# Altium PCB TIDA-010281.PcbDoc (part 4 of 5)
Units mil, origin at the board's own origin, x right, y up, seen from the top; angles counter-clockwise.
Board outline 3455.86 x 1121.8 mil, 8 copper layers (Top Layer, GND1, Sig1, PWR1, PWR2, Sig2, GND2, Bottom Layer), stack 59.155 mil thick; 291 components, 180 nets, 941 pads, 539 vias.
Unrouted connection lines stored in the file: 41.
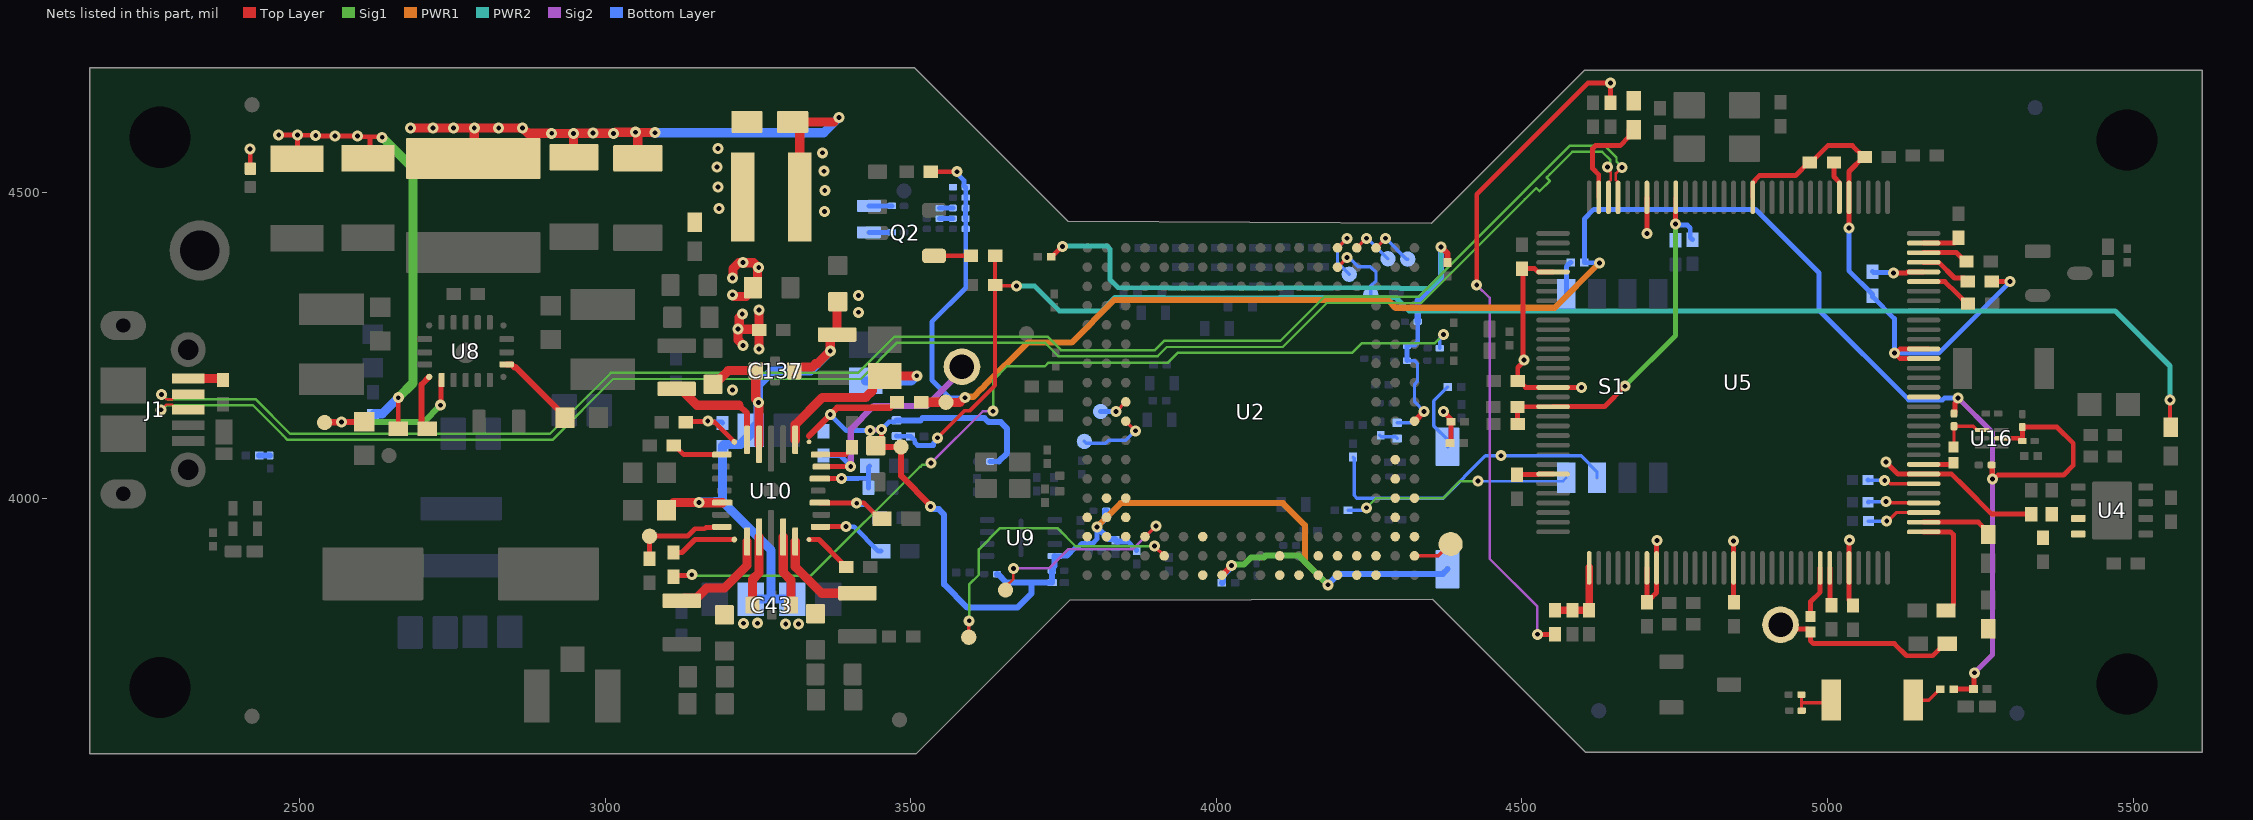
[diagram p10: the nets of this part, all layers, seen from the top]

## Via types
v1: diameter 18, hole 8, Top Layer to Bottom Layer, tented both sides, 533 vias
v2: diameter 19.68, hole 7.87, Top Layer to Bottom Layer, 5 vias
v3: diameter 17, hole 8, Top Layer to Bottom Layer, tented both sides, 1 vias

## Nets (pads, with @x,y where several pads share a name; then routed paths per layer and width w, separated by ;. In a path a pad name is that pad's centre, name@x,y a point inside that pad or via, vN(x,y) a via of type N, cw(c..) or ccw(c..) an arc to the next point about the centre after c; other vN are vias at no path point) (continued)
NetQ2_1: Q2.1 R106.2 | length 60.4
  Top Layer w8: Q2.1@3538.2,4396.29 3538.29,4396.39 3598.44,4396.39 R106.2@3598.54,4396.48
NetR2_2: R2.2 R174.1 | length 30.8
  Bottom Layer w5.5: R174.1@4267.1,4102.78 4269.74,4100.14 4293.06,4100.14 R2.2@4295.7,4097.5
NetR16_2: R16.2 S1.5 | length 55.6
  Bottom Layer w8: S1.5@4572.7,4333.33 4572.7,4378.9 4579.22,4385.42 R16.2@4580.01,4385.42
NetR51_2: R51.2 U5.33 | length 182
  Top Layer w8: U5.33@5157.18,3944.78 5201.19,3944.78 5205.88,3940.09 5205.88,3828.55 5205.59,3828.26 5205.59,3823.86 5197.78,3816.05 R51.2@5193.84,3816.05
NetR57_1: R57.1 U5.95 | length 164.5
  Top Layer w8: U5.95@4625.69,4492.02 4625.62,4492.08 4625.62,4529.3 4615.63,4539.29 4615.63,4572.01 4620.32,4576.7 4660.61,4576.7 4674.85,4590.94 4674.85,4602.5 R57.1@4676.04,4603.7
NetR63_2: R63.2 U5.34 | length 116.1
  Top Layer w8: U5.34@5157.18,3960.53 5246.65,3960.53 5262.71,3944.46 R63.2@5262.71,3940.52
NetR66_1: R66.1 U5.35 | length 96.2
  Top Layer w5.5: v1(5096.82,3962.19) 5098.35,3962.19 5112.43,3976.27 U5.35@5157.18,3976.27
  Bottom Layer w5.5: R66.1@5066.81,3962.19 v1(5096.82,3962.19)
NetR67_1: R67.1 U5.36 | length 92.2
  Top Layer w5.5: v1(5095.54,3994.44) 5097.5,3992.48 5156.73,3992.48 U5.36@5157.18,3992.02
  Bottom Layer w5.5: R67.1@5067.14,3993.8 v1@5094.9,3993.8
  Bottom Layer w8: R67.1@5066.49,3993.15 R67.1@5067.14,3993.8 ; v1@5094.9,3993.8 v1(5095.54,3994.44)
NetR69_1: R69.1 U5.38 | length 93.2
  Top Layer w5.5: v1(5093.53,4028.99) 5096.91,4028.99 5102.38,4023.52 U5.38@5157.18,4023.52
  Bottom Layer w5.5: R69.1@5066.69,4029.21 v1@5093.31,4029.21
  Bottom Layer w8: R69.1@5066.47,4029.42 R69.1@5066.69,4029.21 ; v1@5093.31,4029.21 v1(5093.53,4028.99)
NetR70_1: R70.1 U5.40 | length 50.3
  Top Layer w8: U5.40@5157.18,4055.01 5157.24,4055.08 5203.61,4055.08 R70.1@5206.3,4057.77
NetR71_2: R71.2 U5.25 | length 85.7
  Top Layer w8: R71.2@4972.14,3806.56 4972.14,3830.46 4987.89,3846.2 U5.25@4987.89,3885.72
NetR72_1: R72.1 U5.63 | length 62
  Top Layer w8: U5.63@5157.18,4417.22 5207.43,4417.22 5214.37,4424.16 R72.1@5214.37,4426.13
NetR73_1: R73.1 U5.62 | length 76.1
  Top Layer w8: U5.62@5157.18,4401.47 5210.94,4401.47 5225.37,4387.04 R73.1@5227.34,4387.04
NetR74_1: R74.1 U5.61 | length 85
  Top Layer w8: U5.61@5157.18,4385.72 U5.61@5157.18,4385.72 5182,4385.66 5207.62,4360.04 5223.3,4360.04 R74.1@5229.15,4354.19
NetR76_1: R76.1 U5.60 | length 85.3
  Top Layer w8: v1(5108.12,4368.1) 5129.12,4368.1 5130.93,4369.91 5157.12,4369.91 U5.60@5157.18,4369.97
  Bottom Layer w8: R76.1@5073.68,4370.52 5074.89,4369.31 5106.92,4369.31 v1(5108.12,4368.1)
NetR87_1: R87.1 U5.70 | length 60.9
  Top Layer w8: R87.1@5010.5,4549.28 5010.5,4525.67 5019.39,4516.78 U5.70@5019.39,4492.02
NetR90_2: R90.2 U5.59 | length 87.5
  Top Layer w8: U5.59@5157.18,4354.23 U5.59@5157.18,4354.23 5192.03,4354.16 5211.29,4334.91 5211.29,4334.84 5227.79,4318.34 R90.2@5229.76,4318.34
NetR91_2: R91.2 R141.1 U10.4 | length 160.6
  Top Layer w8: U10.4@3351.28,3992.35 3351.67,3991.96 3411.13,3991.96 v1(3411.52,3991.57) ; v1@3411.52,3992.35 3423.13,3992.35 3449.11,3966.37 R141.1@3453.05,3966.37
  Bottom Layer w8: v1(3411.52,3991.57) 3413.43,3989.66 3425.57,3989.66 3447.41,3967.81 R91.2@3449.38,3967.81
NetR92_2: R92.2 TP12.1 U10.7 | length 390.3
  Top Layer w8: U10.7@3353.74,4051.41 3354.22,4051.88 3401.38,4051.88 v1(3401.76,4051.5)
  Sig2 w10: v1(3401.76,4051.5) 3401.76,4112.92 3439.51,4150.66 3526.18,4150.66 3583.71,4208.2 TP12.1@3583.71,4214.86
  Bottom Layer w8: R92.2@3357.44,4069.66 3384.6,4069.66 3401.76,4052.51 v1(3401.76,4051.5)
NetR94_2: R94.2 U10.16 | length 84.9
  Top Layer w8: R94.2@3112.06,4085.88 3114.03,4085.88 3128.82,4071.09 U10.16@3190.85,4071.09
NetR110_1: R110.1 U8.1 | length 95.5
  Top Layer w10: R110.1@2708.74,4113.26 2706.28,4113.26 2699.47,4120.07 2699.47,4185.71 U8.1@2712.02,4198.31 U8.1@2712.02,4198.31
NetR111_1: R111.1 SW3.2 | length 51.6
  Top Layer w5.5: SW3.2@5140.04,3669.47 5165.61,3669.47 5183.47,3687.32 R111.1@5184.25,3687.32
NetR113_2: R113.2 TP1.1 U8.2 | length 280.7
  Top Layer w8: v1(2730.48,4151.88) 2731.52,4152.93 2731.52,4192.22 U8.2@2732.45,4193.15
  Top Layer w10: TP1.1@2540.97,4123.57 2541.39,4123.99 2568.46,4123.99 v1(2568.88,4124.41) 2605.37,4124.41 R113.2@2605.99,4125.03
  Sig1 w10: v1(2568.88,4124.41) 2703,4124.41 v1(2730.48,4151.88)
NetR125_2: R125.2 R129.1 SW3.1 | length 77
  Top Layer w5.5: R125.2@4957.26,3678.43 4957.37,3678.32 4957.37,3665.25 ; R129.1@4957.48,3652.08 4957.37,3652.18 4957.37,3665.25 ; SW3.1@5006.18,3669.47 5001.97,3665.25 4957.37,3665.25
NetR127_2: R127.2 U10.23 | length 108.1
  Top Layer w8: R127.2@3112.06,3910.9 3125.64,3910.9 3146.87,3932.13 U10.23@3211.33,3932.13
NetR131_2: R131.2 TP10.1 U10.22 | length 161.3
  Top Layer w8: R131.2@3072.69,3900.86 TP10.1@3072.69,3937.64 3134.7,3937.64 3146.89,3949.83 3162.88,3949.83 3165.12,3952.06 3189.93,3952.06 U10.22@3190.85,3952.98
NetR134_1: R134.1 U10.1 | length 80.7
  Top Layer w8: U10.1@3333.5,3932.13 3349.87,3932.13 3386.71,3895.29 3386.71,3893.32 3392.55,3887.48 R134.1@3394.52,3887.48
NetR136_1: R136.1 U10.8 | length 57.9
  Top Layer w8: U10.8@3352.27,4071.09 3393.71,4071.09 3403.94,4081.33 R136.1@3403.94,4083.29
NetR139_2: R139.2 U10.2 | length 115.5
  Top Layer w8: U10.2@3352.27,3952.98 3352.46,3953.18 3393.84,3953.18 v1(3394.04,3953.38)
  Bottom Layer w8: v1(3394.04,3953.38) 3394.43,3952.99 3407.35,3952.99 3447.06,3913.28 R139.2@3451,3913.28
NetR176_1: R176.1 S3.1 | length 117
  Bottom Layer w5.5: S3.1@4378.33,4083.66 4378.33,4095.26 4355.69,4117.91 4355.69,4158.92 R176.1@4378.58,4181.8
NetTP2_1: TP2.1 U2.C10 | length 47.8
  Top Layer w5.5: v1(3836.01,4141.61) U2.C10@3851.76,4157.36
  Bottom Layer w8: TP2.1@3810.59,4141.77 3835.85,4141.77 v1(3836.01,4141.61)
NetTP3_1: TP3.1 U2.C9 | length 115.7
  Top Layer w5.5: U2.C9@3851.76,4125.86 v1(3867.5,4110.11)
  Bottom Layer w5.5: TP3.1@3784,4092.76 3787.31,4089.45 3818.58,4089.45 3823.59,4094.46 3851.85,4094.46 v1(3867.5,4110.11)
NetTP6_1: TP6.1 U2.T18 | length 72.5
  Top Layer w5.5: U2.T18@4261.2,4409.33 v1(4276.95,4425.07)
  Bottom Layer w5.5: v1(4276.95,4425.07) 4311.08,4390.94 TP6.1@4313,4390.94
NetTP7_1: TP7.1 U2.R18 | length 71.4
  Top Layer w5.5: U2.R18@4229.71,4409.33 v1(4245.46,4425.07)
  Bottom Layer w5.5: v1(4245.46,4425.07) 4247.21,4425.07 TP7.1@4280.69,4391.59
NetTP8_1: TP8.1 U2.P17 | length 119.9
  Top Layer w5.5: U2.P17@4198.21,4377.83 v1(4213.96,4393.58)
  Bottom Layer w5.5: v1(4213.96,4393.58) 4217.13,4393.58 4231.98,4378.73 4251.94,4378.73 4261.2,4369.47 4261.2,4355.69 4252.7,4347.19 TP8.1@4252.7,4332.6
NetTP9_1: TP9.1 U2.P18 | length 95.6
  Top Layer w5.5: U2.P18@4198.21,4409.33 v1(4213.96,4425.07)
  Bottom Layer w5.5: v1(4213.96,4425.07) 4198.22,4409.33 4198.22,4385.27 TP9.1@4217.3,4366.19
NetTP11_1: TP11.1 U2.V2 | length 67.1
  Top Layer w5.5: U2.V2@4324.2,3905.39 4363.06,3905.39 4382.34,3924.67 TP11.1@4383.28,3924.67
NetTP23_1: TP23.1 U2.E2 | length 487.3
  Top Layer w5.5: TP23.1@3594.89,3772.36 3594.89,3798.48 v1(3595.64,3799.22) ; v1(3898.66,3921.37) v1(3898.66,3921.37) U2.E2@3914.75,3905.39 U2.E2@3914.75,3905.39
  Sig1 w4.2: v1@3595.41,3799.22 3595.41,3858.46 3611.5,3874.56 3611.5,3915.97 3646.32,3950.8 3740,3950.8 3769.66,3921.14 3898.43,3921.14 v1(3898.66,3921.37)
NetTP24_1: TP24.1 U2.D3 | length 327.5
  Top Layer w4.2: TP24.1@3655,3849.49 3655,3855.11 3667.82,3867.93 v1(3667.82,3885.04)
  Top Layer w5.5: U2.D3@3883.25,3936.89 3883.51,3936.89 3900.74,3954.12 v1(3901,3954.12)
  Sig2 w4.2: v1(3667.82,3885.04) 3726.36,3885.04 3757.68,3916.36 3863.24,3916.36 v1(3901,3954.12)
NetU2_A3: U2.A3
NetU2_A4: U2.A4
NetU2_B3: U2.B3
NetU2_B4: U2.B4
NetU2_B5: U2.B5
NetU2_C3: U2.C3
NetU2_C4: U2.C4
NetU2_C5: U2.C5
NetU2_G1: U2.G1
NetU2_G3: U2.G3
NetU2_L1: U2.L1
NetU2_L2: U2.L2
NetU2_M1: U2.M1
NetU2_N1: U2.N1
NetU2_N2: U2.N2
NetU2_P1: U2.P1
NetU2_P2: U2.P2
NetU2_R1: U2.R1
NetU2_R2: U2.R2
NetU2_T1: U2.T1
NetU2_T2: U2.T2
NetU2_U3: U2.U3
NetU2_U4: U2.U4
NetU2_U5: U2.U5
NetU2_U6: U2.U6
NetU2_U7: U2.U7
NetU2_V3: U2.V3
NetU2_V5: U2.V5
nFAULT: R114.2 U8.8 | length 132.9
  Top Layer w10: U8.8@2838.75,4218.74 2846.73,4218.74 2851.49,4213.97 2853.54,4213.97 2923.35,4144.17 2923.35,4141.91 R114.2@2934.1,4131.16
NRSTOUT: R95.2 R97.2 U10.6 | length 116.5
  Top Layer w8: U10.6@3351.28,4031.72 3351.59,4032.03 3386.41,4032.03 v1(3386.72,4032.33)
  Bottom Layer w8: v1@3387.01,4032.04 3414,4032.04 3414.45,4032.5 3430.69,4032.5 ; R97.2@3430.69,4016.69 3430.69,4032.11 3430.69,4050.47 R95.2@3432.95,4052.72
PGOOD: R18.1 R106.1 R112.2 R118.1 R119.2 | length 2522.3
  Top Layer w6: v1(3543.56,4098.62) 3587.56,4142.62 3596.2,4142.62 3637.91,4184.32 R112.2@3637.91,4348.49 ; R106.1@3637.91,4396.48 R112.2@3637.91,4348.49 ; v1(3672.85,4347.25) 3639.14,4347.25 R112.2@3637.91,4348.49 ; v1(5560.35,4160.61) 5560.35,4116.94 R18.1@5561.26,4116.03
  PWR2 w8: v1(3672.85,4347.25) 3702.15,4347.25 3743.21,4306.19 3812.27,4306.19 3834.16,4328.08 3915.53,4328.08 3916.17,4327.45 4102.47,4327.45 4103.11,4328.08 4136.33,4328.08 4136.47,4327.94 4196.96,4327.94 4197.1,4328.08 4293.3,4328.08 4315.19,4306.19 5470.25,4306.19 5560.35,4216.09 v1(5560.35,4160.61)
  Bottom Layer w8: R118.1@3476.67,4101.6 3477.18,4101.09 3499.01,4101.09 R119.2@3499.52,4100.58 3500.31,4100.58 3506.48,4094.41 3506.48,4090.97 3511.17,4086.29 3537.17,4086.29 3537.17,4089.52 3543.56,4095.91 v1(3543.56,4098.62)
PMIC_3V3: C87.1 C88.1 C100.1 C101.1 C102.1 C108.2 L12.1 R2.1 R4.1 R5.1 R9.1 R21.2 R22.2 R23.2 R43.2 R44.2 R45.2 R59.2 R75.1 R118.2 S3.2 TP22.1 U2.H1 U2.V9 U9.8 U10.9 | length 3607.2
  Top Layer w8: C108.2@3442.7,4085.55 3452.05,4094.9 v1(3452.05,4112.26) ; R4.1@3729.77,4394.61 3730.56,4394.61 3747.84,4411.89 v1(3748.45,4411.89) ; v1(4371.44,4141.61) 4383.88,4129.17 C88.1@4383.88,4124.76 4383.88,4094.76 C102.1@4379.37,4090.24
  Top Layer w10: 3333.5,4101.76 3379.44,4147.7 3466.41,4147.7 3475.47,4156.76 L12.1@3477.44,4156.76 ; C108.2@3444.51,4083.73 TP22.1@3484.04,4083.73 3484.04,4036.21 3532.57,3987.67 v1(3532.57,3985.89) ; U2.H1@4009.24,3873.89 v1(4024.98,3889.64) ; U2.V9@4324.2,4125.86 v1(4339.94,4141.61) ; v1(4367.63,4410.91) 4378.13,4400.41 R5.1@4378.13,4385.29
  Sig1 w10: v1(4024.98,3889.64) 4026.51,3891.17 4045.15,3891.17 4056.59,3902.61 4077.62,3902.61 4080.73,3905.71 4134.9,3905.71 v1(4182.46,3858.15)
  PWR1 w10: v1(3804.51,3952.63) 3843.5,3991.63 4108.76,3991.63 4144.85,3955.54 4144.85,3895.76 v1(4182.46,3858.15)
  PWR2 w8: v1(3748.45,4411.89) 3749.13,4412.58 3821,4412.58 3825.69,4407.89 3825.69,4357.6 3839.21,4344.08 3922.16,4344.08 3922.79,4343.45 4095.85,4343.45 4096.48,4344.08 4142.96,4344.08 4143.1,4343.94 4190.33,4343.94 4190.47,4344.08 4299.92,4344.08 4300.92,4343.08 4347.81,4343.08 4367.63,4362.9 v1(4367.63,4410.91)
  Sig2 w8: v1(3433.61,4110.29) 3434.6,4111.28 3451.07,4111.28 v1(3452.05,4112.26)
  Bottom Layer w5.5: R2.1@4295.7,4123.1 4321.43,4123.1 v1(4339.94,4141.61) 4324.2,4157.36 4324.2,4186.5 4329,4191.3 4329,4220.2 4324.44,4224.76 R59.2@4311.76,4224.76
  Bottom Layer w8: v1(3368.32,4136.58) 3394.6,4110.29 v1(3433.61,4110.29) ; v1(3452.05,4112.26) 3452.05,4112.45 3464.46,4124.85 3474.33,4124.85 R118.2@3476.67,4127.2 ; R44.2@3629.89,4059.85 3643.99,4059.85 ; U9.8@3735.4,3905.15 3755.66,3905.15 3769.33,3918.82 3772.88,3918.82 3779.79,3925.72 3797.44,3925.72 3804.51,3932.79 v1(3804.51,3952.63) ; 3854.71,3929.13 3866.52,3917.33 3867.3,3917.33 3869.6,3915.03 R75.1@3869.6,3914.24 ; R59.2@4311.76,4224.76 R23.2@4311.76,4249.29 4313.12,4250.65 4324.8,4250.65 4329.48,4255.34 R22.2@4329.48,4288.76
  Bottom Layer w10: R118.2@3476.67,4127.2 3515.41,4127.2 3519.23,4131.02 3620.43,4131.02 3627.23,4124.22 3647.19,4124.22 3657.68,4113.73 3657.68,4073.54 3643.99,4059.85 ; v1(3532.57,3985.89) 3533.39,3985.89 3537.46,3981.82 3545.88,3981.82 3554.66,3973.03 3554.66,3858.85 3592.64,3820.87 3674.32,3820.87 3697.56,3844.12 3697.56,3861.85 ; R43.2@3641.22,3875.43 3641.58,3875.06 3642.87,3875.06 3656.09,3861.85 3697.56,3861.85 ; C101.1@3730.99,3881.17 C101.1@3731.2,3881.17 ; U9.8@3735.4,3905.15 3735.4,3889.28 3732.96,3886.83 3732.96,3881.34 3732.79,3881.17 C101.1@3731.2,3881.17 ; R45.2@3819.73,3978.91 3818.44,3978.91 3818.08,3978.55 3818.08,3966.2 v1(3804.51,3952.63) 3823.84,3933.31 3833.7,3933.31 3835,3932.01 R9.1@3835,3931.22 ; R9.1@3835,3930.43 3836.3,3929.13 3854.71,3929.13 ; C87.1@4008.95,3861.38 4009.74,3861.38 4011.04,3862.68 4011.04,3873.53 4024.98,3887.48 v1(4024.98,3889.64) ; v1(4182.46,3858.15) 4200.36,3876.05 4370.48,3876.05 S3.2@4378.13,3883.7 ; R22.2@4329.48,4288.76 R21.2@4329.48,4310.76 4329.48,4322.94 4367.63,4361.09 v1(4367.63,4410.91) ; 3697.56,3861.85 3697.64,3861.77 3731.29,3861.77 C100.1@3731.37,3861.69 3731.37,3880.99 C101.1@3731.2,3881.17
PMIC_5V0: C106.1 C107.1 U10.10 | length 347.6
  Top Layer w15: U10.10@3310.93,4095.21 3310.93,4120.1 3355.53,4164.7 3426.34,4164.7 3437.56,4175.92 3437.56,4185.56 C106.1@3454.51,4202.5 ; C106.1@3457.62,4199.71 3457.82,4199.9 3509.61,4199.9 v1(3509.81,4200.09)
  Bottom Layer w15: C107.1@3426.34,4191.6 3500.5,4191.6 3508.99,4200.09 v1(3509.81,4200.09)
PMIC_CLK: R103.2 R127.1 | length 1479.1
  Top Layer w8: R127.1@3112.06,3871.53 3113.59,3873.07 3140.16,3873.07 v1(3141.7,3874.61)
  Sig1 w4.2: v1(3141.7,3874.61) 3143.34,3872.97 3336.66,3872.97 3514.92,4051.23 3515.96,4051.23 3519.3,4054.56 3530.72,4054.56 v1(3533.36,4057.2) ; v1(3634.65,4142.12) 3634.65,4192.45 3657.87,4215.67 3719.34,4215.67 3725.17,4221.5 3920.94,4221.5 3937.37,4237.93 4222.5,4237.93 4237.56,4252.99 4356.92,4252.99 v1(4371.44,4267.52)
  Sig2 w4.2: v1(3533.36,4057.2) 3618.21,4142.05 v1(3634.65,4142.12) v1(3634.65,4142.12)
  Bottom Layer w5.5: R103.2@4365.65,4245.1 4365.65,4261.72 v1(4371.44,4267.52)
PMIC_EN: R122.1 R123.1 U10.15 | length 120.5
  Top Layer w8: R122.1@3131.74,4124.03 3132.86,4125.14 3166.7,4125.14 v1(3167.82,4126.26) 3169.73,4124.34 3178.94,4124.34 U10.15@3211.33,4091.95
  Bottom Layer w8: v1(3167.82,4126.26) 3169.53,4124.54 3190.49,4124.54 R123.1@3192.2,4122.83
PMIC_INPUT3V3: C131.1 C132.2 C133.2 C134.2 C135.1 L6.2 L8.1 R110.2 R115.2 R120.1 | length 1886.9
  Top Layer w8: v1(2419.11,4570.98) 2419.22,4570.87 2419.22,4538.94 C132.2@2419.33,4538.83 ; v1(2465.87,4593.78) 2466,4593.92 2496.7,4593.92 v1(2496.84,4594.05) ; C135.1@2495.65,4555.28 2496.84,4556.47 v1(2496.84,4594.05) ; C131.1@2611.98,4555.81 2615.09,4558.92 2615.09,4591.18 ; v1(2635.18,4590.27) 2634.27,4591.18 2615.09,4591.18 ; R110.2@2661.5,4113.26 v1(2661.5,4164.2) ; v1(2496.84,4594.05) 2497.25,4593.64 2526,4593.64 v1(2526.41,4593.22) 2526.97,4592.66 2557.67,4592.66 v1(2558.23,4592.1) v1(2595,4592.1) 2595.92,4591.18 2615.09,4591.18
  Top Layer w15: v1(2681.59,4605.33) v1(2718.37,4605.33) v1(2751.54,4605.33) v1(2785.84,4605.33) ; L6.2@2784.02,4555.53 2785.84,4557.35 v1(2785.84,4605.33) ; C133.2@2948.98,4557.72 2948.28,4558.42 v1(2948.28,4596.6) ; v1@3050.07,4598.14 3081.05,4598.14 v1(3081.47,4597.71) ; C134.2@3053.4,4555.84 3053.4,4593.99 3049.65,4597.75 v1(3049.65,4598.56) 3016.67,4598.56 3014.7,4596.59 v1(3013.89,4596.59) 3013.61,4596.87 2980.09,4596.87 v1(2979.81,4597.15) 2979.53,4596.87 2948.56,4596.87 v1(2948.28,4596.6) ; R120.1@3306.67,4615.45 R120.1@3307.6,4615.45 ; L8.1@3318.21,4492.76 3318.21,4604.84 R120.1@3307.6,4615.45 ; 3374.45,4615.45 R120.1@3307.6,4615.45 ; v1(2785.84,4605.33) v1(2825.8,4605.33) v1(2864.39,4605.33) 2865.21,4605.33 2873.66,4596.88 v1(2912.51,4596.88) 2912.65,4596.74 2948.14,4596.74 v1(2948.28,4596.6)
  Sig1 w15: v1(2635.18,4590.27) 2685.56,4539.9 2685.56,4188.25 v1(2661.5,4164.2)
  Bottom Layer w15: R115.2@2620.02,4133.57 2622.36,4135.91 2622.36,4137.88 2635.18,4137.88 v1(2661.5,4164.2) ; v1(3081.47,4597.71) 3357.53,4597.71 v1(3382.35,4622.54)
  other v1: 3358.95,4468.57 3359.32,4503.46 3358.04,4534.73 3355.86,4564.9
PMIC_NINT: R92.1
PS0: R77.2 R93.1 | length 21.6
  Bottom Layer w8: R93.1@3547.14,4457.3 R77.2@3568.78,4457.3
PS1: R78.2 R98.1 | length 21.7
  Bottom Layer w8: R98.1@3547.14,4474.39 3547.22,4474.47 3568.69,4474.47 R78.2@3568.77,4474.55
PVIN3V3: C27.2 C28.2 C29.2 C35.2 C36.1 C37.1 C40.1 C41.1 C42.1 C43.1 C43.3 C48.2 C105.2 C137.1 C137.3 L8.2 L11.2 R120.2 R123.2 U10.13 U10.20 U10.25 U10.27 | length 1660.7
  Top Layer w15: C48.2@3100.25,3980.41 3100.25,3981.39 3108.49,3989.64 3109.28,3989.64 3112.21,3992.57 v1(3153.42,3992.57) 3153.53,3992.46 3191.72,3992.46 U10.20@3191.83,3992.35 ; C28.2@3176.45,4186.04 3184.7,4194.29 3187.1,4194.29 3201.29,4208.47 C137.3@3246.07,4208.47 ; v1(3208.36,4332.59) 3209.17,4332.59 3212.07,4329.69 3230.18,4329.69 3241.85,4341.37 C27.2@3241.85,4344.32 3249.12,4351.58 3249.12,4374.32 3251.22,4376.43 v1(3251.22,4377.24) 3250.41,4377.24 3242.71,4384.94 3226.72,4384.94 v1@3225.93,4385.72 ; v1(3208.44,4360.07) 3209.01,4360.64 3209.01,4375.23 3218.72,4384.94 3224.76,4384.94 v1(3225.33,4385.51) ; v1@3218,4276.15 C37.1@3250.87,4276.15 ; v1(3224.33,4301.35) 3224.33,4300.54 3219.39,4295.6 3219.39,4279.5 3217.42,4277.53 v1(3217.42,4276.72) 3217.42,4258.55 3225.33,4250.64 v1(3225.33,4249.83) ; C43.3@3241.07,3824.82 3241.07,3866.77 3251.87,3877.57 U10.25@3251.87,3936.25 ; C137.3@3246.39,4208.15 3246.39,4161.84 v1@3250.95,4157.27 ; U10.13@3251.87,4087.83 3251.87,4154.73 3251.53,4155.07 3251.53,4155.19 v1@3251.87,4155.54 ; v1(3251.87,4244.1) C37.1@3251.87,4274.8 3251.87,4275.14 C37.1@3250.87,4276.15 ; v1(3251.87,4307.72) 3251.87,4277.15 C37.1@3250.87,4276.15 ; U10.27@3291.24,3936.25 3291.24,3878.58 3304.06,3865.76 C43.1@3304.06,3824.82 ; C137.1@3309.38,4210.12 3313.69,4214.43 3338.92,4214.43 3344.36,4219.87 3347.06,4219.87 3367.51,4240.31 v1(3368.32,4240.31) 3368.32,4263.11 3372.63,4267.43 L11.2@3379.44,4267.43 C105.2@3379.44,4321.35
  Bottom Layer w15: v1(3153.42,3992.57) 3153.99,3993.15 3178.97,3993.15 3179.78,3993.95 3192.2,3993.95 ; C42.1@3238.37,3834.64 3271.56,3834.64 ; C41.1@3306.01,3834.64 3271.56,3834.64 ; v1(3368.32,4240.31) 3335.8,4207.8 3272.92,4207.8 3250.95,4185.83 v1(3250.95,4156.46) 3250.38,4155.89 3250.38,4122.8 C40.1@3238.3,4110.72 3238.3,4104.82 3221.25,4087.77 3194.54,4087.77 3192.2,4085.43 R123.2@3192.2,4083.46 3192.2,3993.95 ; 3192.2,3993.95 3271.56,3914.6 3271.56,3834.64
  other v1: 3295.34,3794.26 3316.2,3794.2 3226.17,3795.1 3249.06,3795.22 3208.44,4176.61 3414.61,4303.98 3414.42,4331.13 3186.1,4473.47 3184.83,4508.74 3183.01,4541.45 3184.83,4572.17
SENS_NRST: R81.2
SOP0: R159.2 S1.3 | length 512.2
  Bottom Layer w5.5: R159.2@4223.5,4067.08 4225.4,4065.18 4225.4,4004.31 4229.83,3999.88 4351.98,3999.88 ; 4351.98,3999.98 4370.9,3999.98 4440.23,4069.31 v1(4465.99,4069.31) 4596.72,4069.31 4622.7,4043.33 S1.3@4622.7,4033.33
SOP1: R171.2 S1.4 | length 379.3
  Sig1 w4.2: v1(4245.46,3984.13) 4260.76,3999.43 4370.7,3999.43 4398.98,4027.72 v1(4428.21,4027.72)
  Bottom Layer w4.2: v1(4428.21,4027.72) 4567.09,4027.72 S1.4@4572.7,4033.33
  Bottom Layer w5.5: R171.2@4215.47,3980.18 4241.5,3980.18 v1(4245.46,3984.13)
SW_B1: L7.1 U10.28 | length 160.9
  Top Layer w15: U10.28@3310.93,3928.87 3310.93,3887.64 3354.26,3844.3 L7.1@3412.67,3844.3
SW_B2: L9.1 U10.24 | length 169.9
  Top Layer w15: L9.1@3125.31,3832.01 3129.63,3836.32 3149.31,3836.32 3165.73,3852.74 3195.09,3852.74 3232.19,3889.84 U10.24@3232.19,3928.87
SW_B3: L10.1 U10.14 | length 185.7
  Top Layer w10: 3218.72,4151.88 3232.19,4138.42 U10.14@3232.19,4095.21
  Top Layer w15: L10.1@3106.76,4179.55 3122.48,4179.55 3150.15,4151.88 3218.72,4151.88
USB_5V: FL2.1 J1.1 | length 58.3
  Top Layer w15: J1.1@2317.73,4195.71 2372.54,4195.71 2374.88,4193.37 FL2.1@2374.88,4193.19
USB_DM: J1.2 U5.93 | length 2754.5
  Top Layer w4: v1(2273.98,4169.36) 2281.76,4161.58 2291.46,4161.58 2300.01,4170.12 J1.2@2317.73,4170.12 ; U5.93@4657.18,4492.02 4657.18,4516.3 4653.56,4519.92 4653.56,4531.32 4663.16,4540.92 v1(4663.71,4540.92)
  Sig1 w4: v1(2273.98,4169.36) 2275.85,4169.36 2283.32,4161.88 2427.86,4161.88 2484.49,4105.26 2909.51,4105.26 3009.08,4204.84 3413.93,4204.84 3473.46,4264.38 3473.56,4264.28 3723.4,4264.28 3745.55,4242.13 3899.6,4242.13 3914.6,4257.13 4104.44,4257.13 4176.5,4329.19 4330.97,4329.19 4578.48,4576.7 4635.24,4576.7 4654.66,4557.27 4654.66,4550.36 4663.71,4541.32 v1(4663.71,4540.92)
USB_DP: J1.3 U5.94 | length 2750.7
  Top Layer w4: v1(2273.44,4144.41) 2273.44,4144.76 2281.76,4153.08 2291.75,4153.08 2300.3,4144.53 J1.3@2317.73,4144.53 ; v1(4639.83,4541.77) 4639.83,4537.98 4645.06,4532.75 4645.06,4519.92 4641.43,4516.3 U5.94@4641.43,4492.02
  Sig1 w4: v1(2273.44,4144.41) 2275.31,4144.41 2282.78,4151.88 2423.72,4151.88 2472.77,4102.83 2480.34,4095.26 2913.65,4095.26 3013.23,4194.84 3418.07,4194.84 3477.51,4254.28 3719.25,4254.28 3741.41,4232.13 3903.75,4232.13 3918.75,4247.13 4108.58,4247.13 4180.64,4319.19 4335.11,4319.19 4504.89,4488.96 4523.27,4507.35 4528.67,4501.95 4545.64,4518.92 4540.24,4524.32 4545.68,4529.75 4582.63,4566.7 4631.1,4566.7 4644.66,4553.13 4644.66,4549.82 4639.83,4544.98 v1(4639.83,4541.77)
VBUS: R64.2 R65.2 | length 17.9
  Bottom Layer w10: R64.2@2433.88,4069.66 2433.95,4069.59 2451.64,4069.59 R65.2@2451.72,4069.52
VBUS_1_DETECT: C16.2 R17.1 R29.2 U5.1 | length 126.8
  Top Layer w12: R17.1@4554.01,3816.35 C16.2@4582.9,3816.35 R29.2@4609.94,3816.35 U5.1@4609.94,3885.72 U5.1@4609.94,3887.25
VCC_BA_3V3: C72.2 L12.2 R13.1 R16.1 R77.1 R78.1 R80.1 R81.1 R82.1 R104.2 R111.2 R124.2 R177.1 R178.1 TP16.1 U16.5 | length 3501.1
  Top Layer w8: R104.2@3533,4533.92 v1(3575.52,4533.92) ; R111.2@5206.3,3687.32 5206.47,3687.49 5238.53,3687.49 R13.1@5238.69,3687.65 5239.54,3688.51 5239.54,3713.26 v1(5240.39,3714.11) ; R177.1@5206.87,4138.44 5208.24,4139.8 5208.24,4155.59 5213.53,4160.88 v1(5213.53,4163.59) ; R178.1@5268.42,4054.09 5269.14,4053.37 5269.14,4032.1 v1(5269.86,4031.37) 5272.57,4031.37 5278.75,4037.55 5386.08,4037.55 5401.95,4053.42 5401.95,4089.6 5375.42,4116.14 R124.2@5318.65,4116.14 C72.2@5318.65,4093.48 5317.48,4094.65 5315.68,4094.65 5312.46,4097.87 U16.5@5284.42,4097.87
  Top Layer w15: L12.2@3516.89,4156.69 TP16.1@3557.44,4156.69 ; TP16.1@3557.51,4156.59 3580.18,4156.59 3587.79,4164.2 v1(3588.6,4164.2)
  PWR1 w10: v1(3588.6,4164.2) 3590.13,4165.73 3602.8,4165.73 3615.55,4178.49 ccw(c3587.75,4211.29) 3620.55,4183.49 3691.44,4254.38 3763.01,4254.38 3832.9,4324.27 4280.06,4324.27 4292.99,4311.34 4553.57,4311.34 v1(4626.81,4384.58)
  Sig2 w8: v1(5213.53,4163.59) 5269.86,4107.25 v1(5269.86,4031.37) 5269.86,3743.58 v1(5240.39,3714.11)
  Bottom Layer w8: v1(3575.52,4533.92) 3575.52,4531.21 3587.32,4519.41 3587.32,4510.18 3588.68,4508.82 R81.1@3589.97,4508.82 R82.1@3589.97,4491.64 3589.89,4491.56 3589.89,4474.63 R78.1@3589.81,4474.55 R77.1@3589.82,4457.3 ; v1(3588.6,4164.2) 3588.46,4164.05 3563.6,4164.05 3534.52,4193.14 3534.52,4288.35 3589.88,4343.72 R80.1@3589.88,4440.29 ; R80.1@3589.88,4440.29 R77.1@3589.85,4457.27 ; v1(4626.81,4384.58) 4626.39,4385 4602.48,4385 R16.1@4602.06,4385.42 4602.06,4456.66 4617.75,4472.36 4882.06,4472.36 4986.02,4368.4 4986.02,4307.3 5132.71,4160.61 5188.53,4160.61 5191.5,4163.59 v1(5213.53,4163.59)
VCC_XDS_3V3: C7.2 C8.2 C9.1 C10.2 C11.1 C12.1 C13.2 C15.2 R20.2 R68.1 R74.2 R76.2 R87.2 R89.2 U4.3 U4.4 U5.7 U5.8 U5.16 U5.26 U5.28 U5.39 U5.47 U5.51 U5.52 U5.69 U5.79 U5.90 U5.101 U5.113 U5.122 | length 2159.6
  Top Layer w8: C10.2@4491.53,4038.27 4526.39,4038.27 4527.39,4039.27 U5.122@4550.88,4039.27 ; U5.101@4550.88,4369.97 4550.82,4370.04 4526.06,4370.04 4520.69,4375.41 C9.1@4499.97,4375.41 4501.71,4373.68 4501.71,4227.68 v1(4503.44,4225.94) 4503.44,4224 4493.09,4213.65 C12.1@4493.09,4191.81 4495.06,4191.81 4505.86,4181 U5.113@4550.88,4181 v1(4597.22,4181) ; U5.7@4704.43,3885.72 4704.49,3885.66 4704.49,3830.12 R89.2@4704.82,3829.79 4704.82,3831.76 4710.66,3837.6 4712.63,3837.6 4720.17,3845.14 U5.8@4720.17,3885.72 4720.24,3885.79 4720.24,3929.97 v1(4720.7,3930.44) ; U5.90@4704.43,4492.02 4704.49,4491.96 4704.49,4433.3 v1(4704.82,4432.97) ; U5.16@4846.16,3885.72 U5.16@4846.16,3885.72 4846.22,3829.71 C8.2@4846.59,3829.34 ; U5.16@4846.14,3885.74 v1(4846.12,3929.8) ; U5.79@4877.65,4492.02 4877.65,4515.52 4881.47,4519.33 4881.47,4520.59 4888.46,4527.58 4947.46,4527.58 4969.16,4549.28 R87.2@4971.13,4549.28 4973.1,4549.28 5000.52,4576.7 5040.61,4576.7 5059.04,4558.28 5035.13,4534.37 U5.69@5035.13,4492.02 U5.69@5035.13,4492.02 5035.07,4441.95 v1(5034.82,4441.71) ; U5.26@5003.64,3885.72 5003.7,3885.66 5003.7,3827.36 C11.1@5006.67,3824.39 ; v1(5035.67,3931.06) 5035.2,3930.59 5035.2,3885.79 U5.28@5035.13,3885.72 5035.13,3832.82 5041.78,3826.18 C7.2@5041.78,3824.21 ; v1(5095.54,4058.9) 5115.11,4039.33 5157.12,4039.33 U5.39@5157.18,4039.27 5203.09,4039.27 5223.49,4018.86 5268.66,3973.69 C15.2@5333.26,3973.69 ; v1(5109.37,4237.13) v1@5109.78,4237.13 ; U5.51@5157.18,4228.24 5118.68,4228.24 v1@5109.78,4237.13 ; U5.52@5165.61,4243.99 U5.52@5157.18,4243.99 5118.68,4243.99 5111.82,4237.13 v1@5109.78,4237.13 ; R74.2@5268.52,4354.19 v1@5298.74,4354.18
  Bottom Layer w8: v1(5034.82,4441.71) 5034.82,4371.97 5073.68,4333.12 R76.2@5073.68,4331.15 5073.68,4329.18 5109.37,4293.49 v1(5109.37,4237.13) 5181.72,4237.13 v1(5298.75,4354.16)
VDDC_1: C17.2 C18.2 C19.2 C20.1 U5.87 U5.115 | length 635.9
  Top Layer w8: C17.2@4492.81,4120.8 4492.74,4120.87 4492.74,4148.84 C18.2@4492.67,4148.91 4493.2,4149.44 4550.82,4149.44 U5.115@4550.88,4149.5 4634.95,4149.5 v1(4668.4,4182.95) ; v1(4751.18,4448.48) 4751.18,4468.03 4751.67,4468.53 U5.87@4751.67,4492.02
  Sig1 w8: v1(4668.4,4182.95) 4751.18,4265.73 v1(4751.18,4448.48)
  Bottom Layer w8: v1(4751.18,4448.48) v1@4751.29,4448.36 ; C19.2@4751.4,4421.5 4751.29,4421.61 v1@4751.29,4448.36 ; C20.1@4778.85,4422.75 4775.35,4426.25 4775.35,4441.88 4770.66,4446.56 4753.09,4446.56 v1@4751.29,4448.36
XDS_NRST: R70.2 R177.2 U16.1 | length 82.3
  Top Layer w5.5: R70.2@5206.3,4083.75 5206.87,4084.33 R177.2@5206.87,4117.41 5238.7,4117.41 5244.45,4111.65 U16.1@5252.92,4111.65
XDS_UARTA_RX: R30.1
XDS_UARTA_TX: R38.1 R71.1 TP5.1 | length 310.5
  Top Layer w8: TP5.1@4923.05,3792.76 4930.19,3785.63 4967.87,3785.63 4972.14,3781.36 R71.1@4972.14,3780.57 4972.14,3766.56 4976.83,3761.87 5109.37,3761.87 5129.18,3742.06 5171.88,3742.06 5191.7,3761.87 R38.1@5195.63,3761.87
XDSET_1_ID: R57.2
XDSET_1_VBUS: R17.2 R39.2 | length 1115.9
  Top Layer w8: v1(4425.97,4348.87) 4425.97,4496.91 4607.88,4678.82 v1(4644.85,4678.82) 4644.7,4678.67 4644.7,4647.16 R39.2@4644.55,4647.01 ; v1(4525.22,3777.14) 4525.3,3777.06 4553.92,3777.06 R17.2@4554.01,3776.98
  Sig2 w4.2: v1(4425.97,4348.87) 4447.25,4327.58 4447.25,3900.49 4525.22,3822.53 v1(4525.22,3777.14)
XIN32: C38.1 Y4.1 | length 37.7
  Bottom Layer w8: Y4.1@3431.38,4478.08 C38.1@3469.07,4478.08
XOUT32: C39.1 Y4.2 | length 37.7
  Bottom Layer w8: Y4.2@3431.38,4434.78 C39.1@3469.07,4434.78
pads on no net: Designator23. Designator24. Designator25. Designator26. FID1.1 FID2.1 FID3.1 FID4.1 FID5.1 FID6.1 J1.4 J9.2@3005.31,3676.11 J9.3@2887.2,3676.11 S1.1 S1.2 U4.7 U4.9@5465.42,3954.78 U4.9@5465.42,4004.38 U5.2 U5.3 U5.4 U5.5 U5.6 U5.11 U5.12 U5.13 U5.14 U5.15 U5.18 U5.19 U5.20 U5.21 U5.22 U5.23 U5.24 U5.27 U5.29 U5.30 U5.31 U5.32 U5.41 U5.42 U5.43 U5.44 U5.45 U5.46 U5.49 U5.50 U5.53 U5.54 U5.56 U5.57 U5.65 U5.67 U5.71 U5.72 U5.73 U5.74 U5.75 U5.76 U5.77 U5.78 U5.81 U5.82 U5.83 U5.84 U5.85 U5.86 U5.91 U5.92 U5.97 U5.98 U5.99 U5.100 U5.102 U5.103 U5.104 U5.105 U5.106 U5.107 U5.108 U5.109 U5.110 U5.111 U5.112 U5.116 U5.117 U5.118 U5.119 U5.120 U5.121 U5.123 U5.124 U5.125 U5.126 U5.127 U5.128 U6.3 U8.10 U8.12 U8.16 U8.18

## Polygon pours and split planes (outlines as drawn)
5V_IN on Top Layer "TOP_LAYER_5V_IN" (solid, pour order 753): 2352.93,4080.37 2352.79,4084.09 2431.33,4084.09 2431.33,4008.94 2428.59,4006.2 2413.46,4006.2 2413.46,3927.51 2414.75,3926.22 2306.61,3926.22 2306.61,3960.01 2306.77,3959.85 2353.6,3959.85
VCC_XDS_3V3 on Top Layer "TOP_LAYER_VCC_XDS_3V3_P733" (solid, pour order 733): 5209.91,4607.94 4558.08,4607.94 4472.27,4522.12 4474.86,4026.61 4509.3,4026.61 4509.3,3940.39 4472.27,3940.39 4472.27,3811.06 5441.99,3811.06 5441.99,3915.73 5429.77,3915.02 5429.06,3915.73 5429.06,3981.34 5393.59,3981.34 5315.2,4059.73 5315.2,4607.94
GND on Top Layer "TOP_LAYER_GND_P759" (solid, pour order 759): 5612.71,3584.22 5612.59,3584.34 5612.59,4697.04 4602.91,4697.04 4602.91,4696.96 4353.59,4447.64 3759.21,4447.64 3506.33,4700.53 3506.33,4703.79 2156.95,4703.79 2156.94,4703.79 2156.94,3584.48 2157.05,3584.38 2157.07,3584.4 3508.5,3584.4 3758.77,3834.67 4354.2,3834.67 4604.65,3584.22
AR_1P2 on Top Layer "NONET_L-01_P-001" (solid, pour order 752): 4461.55,4354.72 4461.55,4187.43 4284.83,4187.43 4284.83,4354.72
AR_1P2 on Top Layer "NONET_L-01_P-001" (solid, pour order 738): 3815.53,3844.61 3815.64,3844.71 4142.42,3844.71 4142.42,3899.15 4128.31,3913.26 3815.53,3913.26
GND on Top Layer "TOP_LAYER_GND_P724" (solid, pour order 724): 5126.81,4338.35 5375.42,4338.35 5375.42,4282.01 5361.73,4268.32 5126.81,4268.32
AGND on Top Layer "TOP_LAYER_AGND_P737" (solid, pour order 737): 3228.51,4049.5 3228.63,4049.62 3250.21,4049.62 3250.21,4036 3252.19,4034.02 3289.04,4034.02 3291.71,4036.69 3291.71,4049.9 3307.95,4049.9 3334.22,4023.63 3334.22,4004.33 3301.37,3971.48 3289.89,3971.48 3289.89,3988.35 3281.33,3996.9 3280.94,3996.51 3256.1,3996.51 3249.35,3989.76 3249.35,3974.41 3230.18,3974.41 3229.25,3975.34 3229.25,3988.35 3211.86,4005.74 3211.86,4019.1 3224.87,4032.12 3225.9,4046.46 3228.52,4049.5
VCC_XDS_3V3 on Top Layer "TOP_LAYER_VCC_XDS_3V3_P723" (solid, pour order 723): 5310.37,3992.81 5391.12,3992.81 5391.12,3979.6 5391.05,3979.52 5391.57,3979 5426.72,3979 5426.72,3917.28 5426.65,3917.2 5426.57,3917.28 5310.74,3917.28 5310.74,3992.44
AR_NRST_2 on Top Layer "TOP_LAYER_AR_NRST_2_P721" (solid, pour order 721): 5274.6,4109.62 5300.35,4109.62 5300.35,4128.95 5388.12,4129.95 5383.58,4264.85 5283,4264.85 5271.91,4264.85
NetD1_2 on Top Layer "TOP_LAYER_NETD1_2_P719" (solid, pour order 719): 2359.5,4171.27 2397.31,4171.27 2397.31,4084.42 2395.83,4085.9 2358.59,4085.9 2359.18,4086.48 2359.18,4171.27 2359.65,4171.27 2359.69,4171.3
USB_5V on Top Layer "TOP_LAYER_USB_5V_P718" (solid, pour order 718): 2273.7,4210.56 2354.32,4210.56 2354.32,4216.27 2354.15,4216.44 2354.32,4216.61 2411.91,4216.61 2411.91,4182.69 2411.74,4182.53 2411.57,4182.69 2354.99,4182.69 2354.99,4184.8 2355.1,4184.91 2355,4185 2273.48,4185 2273.48,4210.78
GND on Top Layer "TOP_LAYER_GND_P717" (solid, pour order 717): 2357.67,4221.83 2357.97,4222.13 2419.11,4222.13 2419.11,4225.19 2419.11,4523.1 2375.52,4523.1 2375.28,4523.34 2375.28,4700.4 2374.95,4700.72 2158.75,4700.72 2158.75,3583.42 2158.81,3583.49 2370.5,3583.49 2370.5,3866.65 2367.91,3869.24 2339.59,3869.24 2339.59,4104.96 2253.96,4104.96 2253.93,4104.94 2253.93,4214.75 2253.9,4214.78 2253.9,4219.05 2253.9,4222.13 2419.11,4222.13
GND on Top Layer "TOP_LAYER_GND_P716" (solid, pour order 716): 2471.47,4273.47 3064.46,4273.47 3064.67,4273.68 3065.52,4272.84 3065.52,4165.54 2944.25,4165.54 2885.63,4224.16 2656.38,4224.16 2656.38,4210.96 2601.53,4156.1 2469.46,4156.1 2469.46,4271.46 2471.52,4273.52
NetC117_1 on Top Layer "TOP_LAYER_NETC117_1_P713" (solid, pour order 713): 2672.33,4445.77 2675.02,4448.46 2894.49,4448.46 2894.49,4368.61 2893.69,4367.8 2855.15,4367.8 2797.98,4310.63 2797.98,4284.73 2785.07,4284.73 2766.6,4284.73 2766.6,4367.8 2674.04,4367.8 2672.28,4369.56 2672.28,4447.96 2673.41,4446.82
BUCK_VIN on Top Layer "TOP_LAYER_BUCK_VIN_P712" (solid, pour order 712): 2826.53,4277.38 3065.91,4277.38 3066.19,4277.66 3066.19,4362.08 2884.71,4362.08 2826.25,4303.63 2826.25,4277.66
BUCK_VIN on Top Layer "TOP_LAYER_BUCK_VIN_P711" (solid, pour order 711): 2471.67,4352.28 2663.69,4352.28 2717.38,4298.59 2717.38,4277.66 2471.43,4277.66 2471.43,4277.67 2471.67,4277.91 2471.67,4352.28
GND on Top Layer "TOP_LAYER_GND_P710" (solid, pour order 710): 2389.15,4523.32 2389.37,4523.1 2469.85,4523.1 2469.85,4488.11 2470.62,4487.34 2470.62,4453.44 2666.65,4453.44 2666.9,4453.69 2666.9,4376.84 2667.03,4376.72 2666.78,4376.46 2387.96,4376.46 2389.15,4377.66 2389.15,4523.29
GND on Top Layer "TOP_LAYER_GND_P709" (solid, pour order 709): 2899.44,4471.1 3108.48,4471.1 3108.48,4425 3109.93,4423.55 3164.62,4423.55 3193.52,4394.65 3193.52,4228.26 3152.91,4228.26 3152.91,4308.55 3075.09,4386.37 2900.11,4386.37 2900.11,4470.42
BUCK_VIN on Top Layer "TOP_LAYER_BUCK_VIN_P707" (solid, pour order 707): 3008.12,3817.52 3008.12,4159.12 2941.65,4159.12 2817.6,4061.05 2817.6,3817.81 3008.08,3817.81 3008.2,3817.69
GND on Top Layer "TOP_LAYER_GND_P706" (solid, pour order 706): 2419.33,3996.61 2704.84,3996.61 2704.84,3954.25 2704.84,3730.94 2419.33,3730.94
PMIC_INPUT3V3 on Top Layer "TOP_LAYER_PMIC_INPUT3V3_P704" (solid, pour order 704): 2389.13,4528.67 2388.96,4528.5 2388.96,4590.27 2435.14,4590.27 2489.03,4644.16 3111.28,4644.16 3111.28,4489.64 3111.29,4489.63 2471.48,4489.63 2471.48,4526.53 2471.45,4526.57 2471.41,4526.53 2388.96,4526.53 2388.96,4528.56 2388.86,4528.67
PVIN3V3 on Top Layer "TOP_LAYER_PVIN3V3_P702" (solid, pour order 702): 3281.66,3947.79 3301.62,3947.79 3301.62,3881.09 3362.45,3820.27 3362.45,3772.23 3281.68,3772.23 3281.68,3947.79
GND on Top Layer "TOP_LAYER_GND_P700" (solid, pour order 700): 3175.95,3770.94 3364.86,3770.94 3364.86,3592.23 3175.95,3592.23
PVIN3V3 on Top Layer "TOP_LAYER_PVIN3V3_P699" (solid, pour order 699): 3243.26,3948.61 3261.16,3948.61 3261.16,3771.67 3176.45,3771.67 3176.45,3817.99 3239.44,3880.98 3239.44,3948.48 3239.42,3948.49
AR_1V8 on Top Layer "TOP_LAYER_AR_1V8_P698" (solid, pour order 698): 3512.24,3826.53 3512.24,3619.44 3361.13,3619.44 3361.13,3826.53
GND on Top Layer "TOP_LAYER_GND_P697" (solid, pour order 697): 3268.49,4398.52 3402.16,4398.52 3406.04,4394.64 3406.04,4350.88 3355.13,4350.88 3344.41,4340.16 3344.41,4250.55 3337.86,4250.55 3316.73,4229.42 3295.46,4229.42 3295.46,4145.17 3291.12,4145.17 3269.09,4145.17 3269.09,4398.58 3269.04,4398.63
AR_1P0_RF2 on Top Layer "TOP_LAYER_AR_1P0_RF2_P696" (solid, pour order 696): 3100.29,3795.89 3169.38,3795.89 3169.38,3610.38 3055.17,3610.38 3055.17,3794.68 3100.33,3795.93
PMIC_INPUT3V3 on Top Layer "TOP_LAYER_PMIC_INPUT3V3_P695" (solid, pour order 695): 3267.17,4643.13 3401.98,4643.13 3402.32,4643.48 3402.32,4403.88 3402.19,4403.75 3266.83,4403.75 3266.83,4643.12 3266.82,4643.13 3266.83,4643.14 3267.23,4643.14
PVIN3V3 on Top Layer "TOP_LAYER_PVIN3V3_P694" (solid, pour order 694): 3355.53,4344.32 3449.11,4344.32 3449.11,4294.36 3423.08,4294.36 3422.75,4294.03 3422.75,4242.13 3393.21,4242.13 3369.82,4218.74 3345.82,4218.74 3345.82,4214.84 3324.75,4193.76 3299.83,4193.76 3299.83,4226.19 3303.45,4229.81 3328.57,4229.81 3346.85,4248.09 3346.85,4286.65 3355.53,4286.65
AR_1P2 on Top Layer "TOP_LAYER_AR_1P2_P693" (solid, pour order 693): 3053.4,4382.09 3145.58,4382.09 3145.58,4214.28 3069.39,4214.28 3053.4,4230.26
PVIN3V3 on Top Layer "TOP_LAYER_PVIN3V3_P692" (solid, pour order 692): 3265.88,4643.42 3262.04,4114.75 3243.66,4115.17 3220.11,4169.5 3162.52,4168.75 3163.59,4203.54 3205.43,4215.61 3205.43,4392.64 3202.16,4392.64 3165.11,4429.69 3121.33,4429.69 3121.33,4643.42
GND on Top Layer " " (solid, remove dead copper, pour order 633): 2866.76,4108.87 2874.44,4116.56 2883.51,4116.22 2948.98,4116.22 2955.77,4123.01 2994.86,4123.01 2995.98,4124.13 2995.98,4158.09 2991.86,4160.15 2899.44,4160.15 2889.5,4170.1 2871.02,4170.1 2866.76,4174.36 2866.76,4189.01 2801.59,4189.01 2782.68,4170.1 2782.68,4098.35 2801.42,4079.6 2866.33,4079.6 2866.76,4080.03
PMIC_3V3 on Top Layer " " (solid, remove dead copper, pour order 463): 4333.76,4153.15 4380.42,4153.15 4392.49,4141.09 4392.49,4077.96 4369.74,4077.96 4327.78,4119.92 4327.78,4146.94 4333.32,4152.48
GND on Top Layer " " (solid, remove dead copper, pour order 461): 4193.96,4266.52 3921,4266.52 3921,4014.47 4193.96,4014.47
AR_1V8 on Sig2 "SIG2_AR_1V8_P739" (solid, pour order 739): 4163.85,4441.89 4163.79,4441.94 3857.38,4441.94 3825.5,4382.39 3816.81,4294.37 3815.8,4284.22 3759.7,4251.91 3734.06,4239.65 3721.15,4077.99 3780.52,4077.99 3803.28,4157.39 3885.08,4158.67 3883.65,4237.75 4163.25,4237.75 4163.25,4441.3
GND on Sig2 " " (solid, remove dead copper, pour order 685): 3948.09,4059 3954.56,4052.53 4031.47,4052.53 4046,4038 4046,3978 4128.3,3978 4161.3,4011 4180,4011 4180,4251.36 4232,4303.36 4232,4323.55 3885.08,4323.55 3885.08,4059
PMIC_3V3 on Sig2 "SIG2_PMIC_3V3_P746" (solid, pour order 746): 3370.32,4188.68 3597.82,4188.68 3597.82,4024.31 3611.71,4010.41 3996.64,4010.41 4065.53,3941.52 4295.25,3941.52 4295.25,4347.98 4359.79,4349.04 4417.14,4349.04 4415.71,3856.35 4398.6,3837.23 3554.7,3837.23 3300.16,4114.46
PVIN3V3 on Sig2 "SIG2_PVIN3V3" (solid, pour order 757): 3359.48,4352.42 3457.58,4352.42 3457.58,4266.44 3457.13,4265.99 3457.13,4265.85 3442.31,4254.01 3406.25,4225.94 3358.66,4225.46 3356.35,4225.46 3356.35,4349.29
PVIN3V3 on Sig2 "PVIN3V3_1" (solid, pour order 751): 3143.51,4644.08 3266.37,4644.08 3266.37,4223.31 3268.83,4200.22 3270.62,4057.89 3268.83,4056.1 3241.35,4056.1 3241.35,4137.86 3213.52,4165.69 3143.51,4165.69
VCC_XDS_3V3 on Sig2 "SIG2_VCC_XDS_3V3" (solid, pour order 754): 4569.47,4591.84 5298.75,4591.84 5298.75,4090.01 5330.45,4058.31 5351.13,4058.31 5419.89,3989.56 5419.89,3830.76 4532.16,3830.36 4514.03,3848.07 4514.03,4557.53 4556.59,4591.84
GND on Sig2 "SIG2_GND" (solid, pour order 758): 2156.95,4703.78 2157.01,4703.72 3506.27,4703.72 3506.27,4701.88 3757.42,4450.73 3804.9,4450.73 3807.67,4447.97 4354.35,4447.97 4603.76,4697.38 5610.33,4697.38 5610.59,4697.13 5610.59,3584.74 5610.51,3584.67 5610.42,3584.76 4605.5,3584.76 4351.17,3839.09 3760.83,3839.09 3507.18,3585.44 2161.16,3585.44 2160.99,3585.27 2156.95,3589.31 2156.95,4703.78
BUCK_VIN on Bottom Layer "BOTTOM_LAYER_BUCK_VIN_P708" (solid, pour order 708): 2963.61,4173.11 2818.2,4173.11 2780.86,4135.77 2780.86,4034.15 2693.34,4034.15 2693.16,4034.34 2693.16,3957.67 2713.73,3957.67 2713.07,3934.4 2839.28,3930.53 2839.28,3818.98 3016.96,3818.98 3016.96,4110.5 2963.61,4110.5
GND on Bottom Layer "BOTTOM_LAYER_GND_P734" (solid, pour order 734): 5612.74,3584.2 5612.74,4697.01 4602.91,4697.01 4602.91,4696.94 4353.59,4447.62 3759.21,4447.62 3506.33,4700.5 3506.33,4703.77 2156.95,4703.77 2156.95,3584.46 2157.05,3584.35 2157.07,3584.37 3508.5,3584.37 3758.77,3834.64 4354.2,3834.64 4604.65,3584.2
VCC_BA_3V3 on Bottom Layer "BOTTOM_LAYER_VCC_BA_3V3_P729" (solid, pour order 729): 4525.22,4508.82 4525.48,4509.08 4920.21,4509.08 5027.44,4401.86 5027.44,4323.34 5164.07,4186.71 5415.88,4186.71 5415.88,3851.19 5416.91,3850.16 5296.89,3730.13 5295.16,3730.13 5295.16,3650.23 5265.76,3620.83 5186.55,3620.83 5186.55,4030.35 4817.48,4399.42 4661.56,4399.42 4625.68,4363.54 4526.94,4363.54 4525.22,4365.26
GND on Bottom Layer "BOTTOM_LAYER_GND_P726" (solid, pour order 726): 4612.61,4407.14 4835.39,4407.14 4835.39,4280.94 4835.63,4280.7 4835.52,4280.59 4612.26,4280.59 4612.26,4406.77 4612.62,4407.13
GND on Bottom Layer "BOTTOM_LAYER_GND_P714" (solid, pour order 714): 2468.21,4289.63 2468.19,4289.6 2673.97,4289.6 2673.97,4272 2862.34,4272.01 2862.34,4292.16 2861.17,4293.33 2861.32,4293.47 3067.44,4293.47 3067.44,4112.38 3067.61,4112.22 3067.44,4112.05 2963.43,4112.05 2963.43,4173.58 2963.6,4173.75 2462.81,4173.75 2462.51,4174.05 2462.51,4289.71 2462.6,4289.63 2469.52,4289.63
5V_IN on Bottom Layer "BOTTOM_LAYER_5V_IN_P705" (solid, pour order 705): 2712.42,3731.39 2814.64,3731.39 2814.64,3922.32 2814.88,3922.56 2713.13,3922.56 2712.56,3921.99 2712.56,3730.53
PVIN3V3 on Bottom Layer "BOTTOM_LAYER_PVIN3V3_P703" (solid, pour order 703): 3169.53,4106.52 3169.81,4106.24 3272.54,4106.24 3272.54,4043.43 3272.64,4043.33 3272.54,4043.23 3204.4,4043.23 3204.4,3981.48 3129.32,3981.48 3129.32,4016.97 3129.6,4016.69 3169.53,4016.69 3169.53,4106.35 3169.59,4106.41
PVIN3V3 on Bottom Layer "BOTTOM_LAYER_PVIN3V3_P701" (solid, pour order 701): 3244.66,3956.38 3264.34,3956.73 3335.53,3864.1 3335.53,3769.92 3207.7,3769.92 3207.7,3862.55
AR_1P0_RF2 on Bottom Layer " " (solid, remove dead copper, pour order 687): 4002.3,4262.65 4002.3,4434.54 3979.83,4434.54 3973.82,4434.54 3948.08,4434.64 3948.08,4347.22 3902.1,4347.22 3902.1,4288.23 3902.1,4262.64
AR_1V8 on Bottom Layer "BOTTOM-AR_1V8" (solid, remove dead copper, pour order 669): 3915.56,4106.49 3936.13,4106.49 3936.13,4094.67 4027.05,4003.76 4117.79,4003.76 4117.79,3969.2 3969.04,3969.2 3906.98,4031.26 3877.1,4061.14 3877.1,4115.29 3858.83,4115.29 3841.37,4132.76 3841.37,4145.76 3834.37,4152.76 3823.37,4152.76 3823.37,4184.76 3815,4184.76 3815,4324 3857.74,4324 3857.74,4292.99 3865.06,4285.68 3873.32,4285.68 3876,4282.72 3876,4231 3904.31,4231 3904.31,4214.09 3904,4206.74 3904,4166.83 3904,4126.8 3904,4118.05
5V_IN on Bottom Layer " " (solid, remove dead copper, pour order 661): 2864.39,4252.36 2842.82,4228.87 2784.47,4228.87 2784.47,4319.47 2787.2,4322.2 2864.39,4322.2
GND on Bottom Layer " " (solid, remove dead copper, pour order 647): 2788.04,4340.02 2872.26,4340.02 2872.26,4413.91 2806.29,4413.91 2788.04,4395.66
GND on Bottom Layer " " (solid, remove dead copper, pour order 505): 3926.42,4354.12 3927.43,4353.11 3927.43,4346.38 3941.68,4346.38 3941.69,4434.66 3857.67,4434.66 3857.67,4356.47 3845.29,4344.09 3845.29,4328.08 3846.51,4326.86 3862.3,4326.86 3869.18,4319.97 3869.18,4293.11 3870.15,4292.14 3889.38,4292.14 3889.38,4338.92 3904.58,4354.12
GND on Bottom Layer "Bottom Layer-GND" (solid, remove dead copper, pour order 499): 4097.16,4341.2 4097.16,4362.67 4104.88,4370.38 4126.97,4370.38 4126.97,4399.57 4123.42,4403.12 4122.79,4434.87 4076.41,4434.87 4076.38,4341.2
GND on Bottom Layer "Bottom Layer-GND 1" (solid, remove dead copper, pour order 483): 4039.05,4265.4 4039.05,4433.84 4013.12,4433.84 4013.07,4265.4
PMIC_3V3 on Bottom Layer "Bottom Layer-PMICOUT_3V3" (solid, remove dead copper, pour order 454): 3973.66,3945.37 3982.27,3936.76 3982.28,3886.75 3996.06,3872.97 4015.6,3872.97 4015.6,3844.59 3954.73,3844.59 3934.18,3865.14 3934.18,3915.38 3889.79,3915.38 3882.16,3907.75 3857.31,3907.75 3842.3,3922.76 3794.48,3922.76 3794.48,3968.8 3849.6,3968.8 3849.6,3945.37
AR_1V8 on Bottom Layer "Bottom Layer-BB_1V8" (solid, remove dead copper, pour order 372): 4129.35,4407.73 4135.08,4402.01 4135.08,4354.75 4131.17,4350.83 4103.27,4350.83 4103.27,4328.02 4162.87,4328.02 4162.87,4434.77 4129.35,4434.77
AR_1P0_RF2 on Bottom Layer "Bottom Layer-AR_1P0_RF1" (solid, remove dead copper, pour order 324): 4069.71,4300.36 4069.71,4434.87 4045.46,4434.87 4045.46,4300.36
GND on Bottom Layer "BOTTOM-GND 1" (solid, remove dead copper, pour order 250): 3946.37,4124.5 3949.6,4121.26 3962.92,4121.26 3965.22,4121.27 3971.54,4114.95 3971.54,4089.54 4044.79,4016.28 4203.3,4016.28 4203.3,4099.8 4209.2,4105.7 4223.9,4105.7 4227.1,4108.9 4227.1,4228.46 3946.37,4228.46
AR_1P2 on PWR1 "PWR1_AR_1P2_P740" (solid, pour order 740): 4261.44,4317.9 4437.72,4317.9 4437.72,4178.24 4404.6,4145.12 4404.6,3841.09 3805.93,3844.54 3741.18,4036.33 3814.37,4031.36 3858.61,3991.63 4072.21,3997.59 4279.54,3991.75 4279.54,4218.58 4261.24,4236.88
AR_1P2 on PWR1 "PWR1_AR_1P2" (solid, pour order 749): 3026.77,4329.66 3026.97,4329.86 3224.48,4329.86 3224.48,4105.83 3224.55,4105.76 3224.56,4105.77 3416.59,4105.77 3416.59,4067.91 3416.83,4067.67 3416.7,4067.54 3143.08,4067.54 3026.77,4183.85 3026.77,4329.66
GND on PWR1 "PWR1_GND" (solid, pour order 756): 2156.95,4703.78 2157.01,4703.72 3506.27,4703.72 3506.27,4701.88 3757.42,4450.73 3804.9,4450.73 3807.67,4447.97 4354.35,4447.97 4603.77,4697.38 5610.33,4697.38 5610.59,4697.12 5610.59,3584.74 5610.52,3584.67 5610.43,3584.76 4605.5,3584.76 4351.18,3839.08 3760.83,3839.08 3507.19,3585.43 2161.16,3585.43 2160.99,3585.26 2156.95,3589.3 2156.95,4703.78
